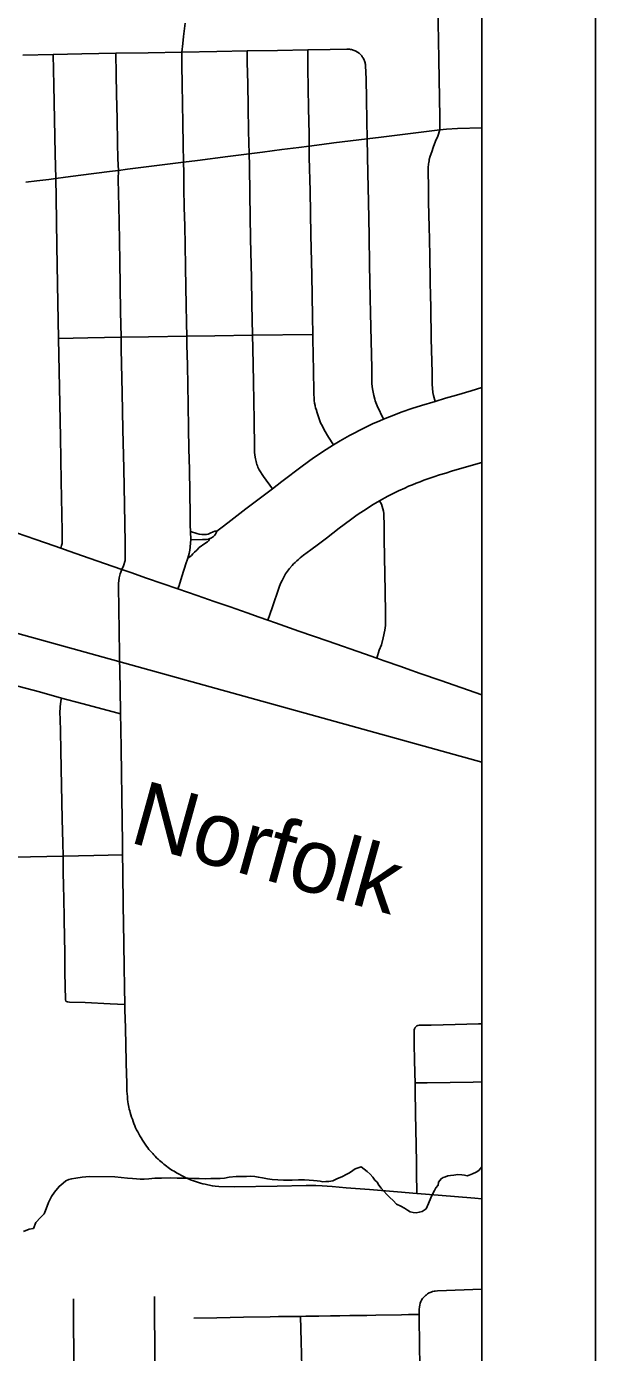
# Model space of a CAD drawing. Extents: x 0 to 34, y -1.2 to 22.
# Drawn here: x 8.499 to 9, y 18.774 to 19.941 of the extents above; entities that cross this region are included whole.
import ezdxf

# ---------------------------------------------------------------- set-up
doc = ezdxf.new("R2010")
doc.units = 0
for name, color, linetype in [('GM_X_City_Street', 7, 'Continuous'), ('GM_X_County_Road', 7, 'Continuous'), ('GM_X_Rail_Line', 7, 'Continuous'), ('GM_X_Rail_Line_Text', 7, 'Continuous'), ('GM_X_State_Route', 7, 'Continuous'), ('SH_Data', 7, 'Continuous')]:
    doc.layers.add(name, color=color, linetype=linetype)

msp = doc.modelspace()

# ---------------------------------------------------------------- linework, layer by layer
at = {"layer": 'GM_X_City_Street'}
for points in [[(8.859, 19.6109), (8.8576, 19.6159), (8.857, 19.6187), (8.8566, 19.6224), (8.8564, 19.6258), (8.8562, 19.636), (8.8555, 19.6662), (8.8554, 19.6744), (8.8551, 19.6847), (8.855, 19.6951), (8.8548, 19.7029), (8.8545, 19.7171), (8.8542, 19.7396), (8.8539, 19.7526), (8.8537, 19.7653), (8.8535, 19.774), (8.8532, 19.7877), (8.8531, 19.8001), (8.8528, 19.8127), (8.8529, 19.8176), (8.853, 19.8188), (8.8531, 19.82), (8.8533, 19.8213), (8.8536, 19.8225), (8.8538, 19.8237), (8.8547, 19.8268), (8.8559, 19.8305), (8.8573, 19.8343), (8.8593, 19.84), (8.8612, 19.8443), (8.8631, 19.85), (8.8631, 19.86), (8.8629, 19.8789), (8.8626, 19.8939), (8.8622, 19.9123), (8.862, 19.9284), (8.8614, 19.9599)], [(8.4962, 19.9157), (8.5228, 19.9163), (8.5481, 19.9167), (8.5781, 19.9173), (8.6064, 19.9178), (8.636, 19.9183), (8.6669, 19.9189), (8.6934, 19.9194), (8.7203, 19.9199), (8.7468, 19.9204), (8.7667, 19.9208), (8.7811, 19.921), (8.7836, 19.9209), (8.7845, 19.9208), (8.7853, 19.9206), (8.7861, 19.9204), (8.7869, 19.9202), (8.7877, 19.9199), (8.7885, 19.9196), (8.7892, 19.9192), (8.7907, 19.9184)], [(8.5295, 19.4815), (8.5303, 19.4841), (8.5307, 19.4858), (8.5309, 19.4876), (8.5308, 19.4966), (8.53, 19.5407), (8.5293, 19.5795), (8.5285, 19.6232), (8.5276, 19.6662), (8.527, 19.6977), (8.5262, 19.7479), (8.5255, 19.7903), (8.5252, 19.8071), (8.5247, 19.8288), (8.524, 19.8589), (8.5234, 19.8892), (8.5228, 19.9163)], [(8.5834, 19.4629), (8.5848, 19.4662), (8.5863, 19.4709), (8.5861, 19.4863), (8.5855, 19.5197), (8.5849, 19.5518), (8.5841, 19.5861), (8.5836, 19.6185), (8.5827, 19.6568), (8.5826, 19.6673), (8.5822, 19.6899), (8.5814, 19.7342), (8.5808, 19.7696), (8.5801, 19.8066), (8.5802, 19.8142), (8.5797, 19.8243), (8.5795, 19.8386), (8.5792, 19.8597), (8.5787, 19.8814), (8.5783, 19.8986), (8.5781, 19.9173)], [(8.7157, 19.534), (8.7078, 19.5447), (8.704, 19.5505), (8.7035, 19.5517), (8.703, 19.5529), (8.7025, 19.5541), (8.7021, 19.5553), (8.7017, 19.5566), (8.7014, 19.5578), (8.7011, 19.5591), (8.7008, 19.5603), (8.7005, 19.5616), (8.7003, 19.5638), (8.7001, 19.566), (8.6999, 19.5704), (8.6996, 19.594), (8.6991, 19.6281), (8.6984, 19.6576), (8.6981, 19.6691), (8.6977, 19.6964), (8.6973, 19.7197), (8.6966, 19.754), (8.6958, 19.7931), (8.6955, 19.8186), (8.6954, 19.8288), (8.6948, 19.8488), (8.6945, 19.87), (8.694, 19.8906), (8.6936, 19.9093), (8.6934, 19.9194)], [(8.7695, 19.5726), (8.7652, 19.5795), (8.7613, 19.5859), (8.7597, 19.589), (8.7589, 19.5905), (8.7582, 19.5921), (8.7569, 19.5954), (8.7563, 19.5972), (8.7551, 19.6009), (8.7542, 19.6039), (8.7538, 19.605), (8.7533, 19.6072), (8.7529, 19.6094), (8.7526, 19.6117), (8.7522, 19.6192), (8.7518, 19.638), (8.7517, 19.6515), (8.7514, 19.6662), (8.7513, 19.6697), (8.751, 19.6856), (8.7503, 19.7224), (8.7496, 19.7571), (8.7489, 19.7961), (8.7482, 19.8256), (8.7482, 19.8355), (8.7481, 19.8461), (8.7475, 19.869), (8.7468, 19.9043), (8.7468, 19.9204)], [(8.8134, 19.5951), (8.8079, 19.6069), (8.8073, 19.6084), (8.8062, 19.6114), (8.8058, 19.6129), (8.805, 19.6159), (8.8043, 19.6189), (8.804, 19.6203), (8.8038, 19.6218), (8.8032, 19.6262), (8.8032, 19.6277), (8.8031, 19.64), (8.8026, 19.6642), (8.8021, 19.6884), (8.8019, 19.7019), (8.8013, 19.7307), (8.8008, 19.7567), (8.8002, 19.7865), (8.7997, 19.8119), (8.7992, 19.842), (8.7988, 19.858), (8.7985, 19.8773), (8.7981, 19.8946), (8.7978, 19.9066), (8.7977, 19.9074), (8.7975, 19.9082), (8.7973, 19.909), (8.7971, 19.9098), (8.7968, 19.9106), (8.7965, 19.9114), (8.7961, 19.9122), (8.7957, 19.9129), (8.7953, 19.9136), (8.7948, 19.9143), (8.7943, 19.915), (8.7938, 19.9157), (8.7933, 19.9163), (8.7927, 19.9169), (8.792, 19.9174), (8.7907, 19.9184)], [(8.5276, 19.6662), (8.5533, 19.6667), (8.5826, 19.6673), (8.6066, 19.6677), (8.6404, 19.6683), (8.665, 19.6687), (8.6981, 19.6691), (8.7513, 19.6697)], [(8.6668, 19.4965), (8.6727, 19.501), (8.6792, 19.506), (8.6924, 19.5162), (8.7063, 19.5267), (8.7157, 19.534), (8.724, 19.5404), (8.7418, 19.5537), (8.752, 19.5612), (8.763, 19.5686), (8.7695, 19.5726), (8.7755, 19.5762), (8.7837, 19.5809), (8.7967, 19.5876), (8.8039, 19.591), (8.8102, 19.5938), (8.8134, 19.5951), (8.8189, 19.5974), (8.8299, 19.6016), (8.8383, 19.6045), (8.8469, 19.6073), (8.859, 19.6109), (8.8681, 19.6136), (8.8778, 19.6163), (8.8906, 19.6201), (8.9, 19.6232)], [(8.7118, 19.4183), (8.7154, 19.4291), (8.7218, 19.4474), (8.723, 19.4504), (8.7243, 19.4533), (8.7257, 19.4561), (8.7273, 19.4589), (8.729, 19.4615), (8.7308, 19.4638), (8.7331, 19.4663), (8.7344, 19.4677), (8.7358, 19.4691), (8.7373, 19.4704), (8.7387, 19.4717), (8.7402, 19.473), (8.7432, 19.4754), (8.7464, 19.4778), (8.7495, 19.4802), (8.7562, 19.4851), (8.7598, 19.4878), (8.7632, 19.4904), (8.7745, 19.4991), (8.7846, 19.5067), (8.7868, 19.5083), (8.7891, 19.51), (8.7913, 19.5115), (8.7936, 19.5131), (8.7959, 19.5146), (8.8045, 19.5202), (8.8101, 19.5234), (8.8174, 19.5274), (8.822, 19.5298), (8.8243, 19.5309), (8.8267, 19.5321), (8.8323, 19.5346), (8.8356, 19.5361), (8.839, 19.5375), (8.8423, 19.5388), (8.8457, 19.5401), (8.849, 19.5414), (8.8524, 19.5427), (8.8577, 19.5444), (8.8629, 19.5461), (8.8682, 19.5478), (8.8734, 19.5493), (8.8928, 19.555), (8.9, 19.5571)], [(8.8075, 19.3848), (8.8098, 19.3917), (8.8116, 19.3964), (8.8132, 19.4028), (8.8148, 19.4095), (8.8152, 19.4135), (8.8154, 19.4227), (8.8149, 19.4453), (8.8148, 19.4572), (8.8144, 19.4752), (8.8141, 19.4885), (8.814, 19.5008), (8.8137, 19.5121), (8.8134, 19.5142), (8.813, 19.5163), (8.8124, 19.5184), (8.8117, 19.5204), (8.8101, 19.5234)], [(8.6438, 19.4962), (8.6493, 19.4945), (8.6514, 19.494), (8.6537, 19.4936), (8.6579, 19.4938), (8.6593, 19.4941), (8.661, 19.4947), (8.6635, 19.496), (8.6651, 19.4965), (8.6668, 19.4965)], [(8.6439, 19.489), (8.6541, 19.4892), (8.6578, 19.4893), (8.6596, 19.4896), (8.6608, 19.49), (8.6617, 19.4904), (8.6635, 19.4917), (8.6648, 19.4928), (8.6658, 19.494), (8.6664, 19.4952), (8.6668, 19.4965)], [(8.6413, 19.4729), (8.643, 19.474), (8.6446, 19.4752), (8.6458, 19.4766), (8.6472, 19.4781), (8.6493, 19.48), (8.6514, 19.4821), (8.6564, 19.4858), (8.6585, 19.4873), (8.6595, 19.4882), (8.6601, 19.4889), (8.6608, 19.49)], [(8.5341, 19.0829), (8.5336, 19.0841), (8.5332, 19.1079), (8.533, 19.1249), (8.5324, 19.1543), (8.5321, 19.175), (8.5319, 19.1825), (8.5317, 19.1982), (8.5315, 19.2104), (8.5314, 19.2222), (8.5309, 19.2431), (8.5302, 19.273), (8.5299, 19.2873), (8.5295, 19.3042), (8.5292, 19.32), (8.5289, 19.3318), (8.5288, 19.3365), (8.529, 19.3419), (8.5296, 19.3469), (8.5303, 19.3497)], [(8.3359, 19.2073), (8.3493, 19.2077), (8.3639, 19.208), (8.3913, 19.2084), (8.4198, 19.2088), (8.4482, 19.2092), (8.4768, 19.2097), (8.5029, 19.21), (8.5315, 19.2104), (8.5587, 19.211), (8.5839, 19.2115)], [(8.5341, 19.0829), (8.5347, 19.0825), (8.5355, 19.0822), (8.5372, 19.082), (8.551, 19.0816), (8.5729, 19.0806), (8.5858, 19.08)], [(8.8427, 18.9135), (8.8426, 18.9319), (8.8425, 18.9404), (8.8421, 18.956), (8.8417, 18.9835), (8.8415, 19.0045), (8.8414, 19.0108), (8.8412, 19.0194), (8.8408, 19.0313), (8.8406, 19.0443), (8.8405, 19.051), (8.8406, 19.0576), (8.8408, 19.0584), (8.8411, 19.059), (8.8413, 19.0594), (8.8415, 19.0597), (8.8418, 19.0601), (8.8427, 19.061)], [(8.8427, 19.061), (8.8438, 19.0614), (8.8448, 19.0616), (8.8553, 19.0618), (8.8765, 19.0623), (8.8972, 19.0628), (8.9, 19.0629)], [(8.8414, 19.0108), (8.852, 19.011), (8.8925, 19.0116), (8.9, 19.0118)], [(8.5423, 18.5793), (8.5422, 18.5968), (8.5421, 18.6183), (8.542, 18.65), (8.5417, 18.682), (8.5415, 18.7141), (8.5413, 18.7443), (8.5411, 18.773), (8.5408, 18.7991), (8.5406, 18.8207)], [(8.6138, 18.5808), (8.6137, 18.5894), (8.6136, 18.6111), (8.6134, 18.6355), (8.6133, 18.6551), (8.613, 18.6752), (8.6129, 18.6943), (8.6127, 18.7109), (8.6125, 18.7281), (8.6124, 18.7448), (8.6124, 18.7583), (8.6123, 18.7775), (8.6122, 18.7853), (8.6121, 18.8007), (8.6119, 18.8229)], [(8.6465, 18.8038), (8.6669, 18.8041), (8.6903, 18.8047), (8.7139, 18.805), (8.7212, 18.8051), (8.7327, 18.8052), (8.7406, 18.8052), (8.7452, 18.8054), (8.7567, 18.8055), (8.7668, 18.8057), (8.7751, 18.8058), (8.7838, 18.806), (8.7915, 18.8061), (8.7989, 18.8062), (8.8068, 18.8064), (8.8293, 18.8067), (8.8356, 18.8068), (8.8448, 18.8069)], [(8.7449, 18.5826), (8.7444, 18.6057), (8.744, 18.6275), (8.7437, 18.6464), (8.7434, 18.6717), (8.7428, 18.6956), (8.7422, 18.7164), (8.7421, 18.7285), (8.7418, 18.7493), (8.7416, 18.7609), (8.7411, 18.7832), (8.7406, 18.8052)]]:
    msp.add_lwpolyline(points, dxfattribs=at)
at = {"layer": 'GM_X_County_Road'}
for p, q in [((8.586, 19.0732), (8.5858, 19.08)), ((8.8494, 18.8226), (8.8505, 18.8237))]:
    msp.add_line(p, q, dxfattribs=at)
for points in [[(8.6413, 19.4729), (8.6424, 19.477), (8.643, 19.4799), (8.6434, 19.4826), (8.6437, 19.4864), (8.6439, 19.489), (8.6438, 19.4962), (8.6435, 19.5019), (8.6433, 19.5108), (8.6427, 19.5509), (8.6422, 19.5692), (8.6419, 19.587), (8.6415, 19.6082), (8.6412, 19.6251), (8.6409, 19.6427), (8.6405, 19.6607), (8.6404, 19.6663), (8.6404, 19.6683), (8.6402, 19.6797), (8.64, 19.6962), (8.6397, 19.711), (8.6393, 19.7295), (8.6389, 19.7484), (8.6386, 19.7654), (8.6382, 19.7817), (8.6379, 19.7985), (8.6377, 19.8124), (8.6375, 19.8215), (8.6373, 19.8366), (8.6368, 19.8559), (8.6362, 19.8899), (8.6361, 19.9072), (8.636, 19.9183), (8.6368, 19.9258), (8.6375, 19.932), (8.6389, 19.9437)], [(8.4987, 19.804), (8.5085, 19.805), (8.5189, 19.8063), (8.5252, 19.8071), (8.5337, 19.8082), (8.5471, 19.81), (8.5724, 19.8132), (8.5802, 19.8142), (8.5882, 19.8152), (8.6257, 19.82), (8.6375, 19.8215), (8.6499, 19.823), (8.6765, 19.8264), (8.6954, 19.8288), (8.707, 19.8302), (8.7241, 19.8325), (8.7391, 19.8344), (8.7482, 19.8355), (8.7591, 19.8369), (8.7699, 19.8384), (8.7992, 19.842), (8.8115, 19.8435), (8.8442, 19.8477), (8.8631, 19.85), (8.8688, 19.8505), (8.8786, 19.8511), (8.9, 19.8516)], [(8.6325, 19.4458), (8.6336, 19.4489), (8.636, 19.4566), (8.64, 19.4686), (8.6407, 19.4712), (8.6413, 19.4729)], [(8.5823, 19.3229), (8.5821, 19.3359), (8.5819, 19.3583), (8.5813, 19.3861), (8.5809, 19.4112), (8.5806, 19.4259), (8.5804, 19.4506), (8.5808, 19.4554), (8.5819, 19.4589), (8.5834, 19.4629)], [(8.5834, 19.4629), (8.5911, 19.4601), (8.6049, 19.4553), (8.6325, 19.4458)], [(8.3531, 19.3974), (8.3609, 19.3952), (8.3833, 19.3892), (8.4006, 19.3846), (8.4176, 19.3802), (8.4633, 19.3676), (8.475, 19.3645), (8.4861, 19.3616), (8.5107, 19.355), (8.5303, 19.3497), (8.5481, 19.3449), (8.5755, 19.3375), (8.5821, 19.3359)], [(8.5858, 19.08), (8.5857, 19.0948), (8.5853, 19.1137), (8.5847, 19.1521), (8.5845, 19.1665), (8.5841, 19.1973), (8.5839, 19.2115), (8.5838, 19.2222), (8.5835, 19.2418), (8.5826, 19.3048), (8.5823, 19.3229)], [(8.9, 18.9088), (8.8938, 18.9093), (8.8615, 18.912), (8.8427, 18.9135), (8.8257, 18.9149), (8.8012, 18.9169), (8.7807, 18.9186), (8.7683, 18.9196), (8.7596, 18.9203), (8.7541, 18.9206), (8.7455, 18.9205), (8.72, 18.92), (8.682, 18.9193), (8.6686, 18.9196), (8.6655, 18.9199), (8.6629, 18.9202), (8.6588, 18.9211), (8.6567, 18.9216), (8.6545, 18.9221), (8.6526, 18.9226), (8.6508, 18.9231), (8.649, 18.9236), (8.6473, 18.9242), (8.6455, 18.9249), (8.6437, 18.9256), (8.642, 18.9263), (8.6403, 18.9271), (8.638, 18.9282), (8.6358, 18.9293), (8.6336, 18.9305), (8.6314, 18.9318), (8.6292, 18.933), (8.6278, 18.9338), (8.6265, 18.9346), (8.6252, 18.9355), (8.6239, 18.9364), (8.6227, 18.9374), (8.6215, 18.9384), (8.6203, 18.9394), (8.6189, 18.9404), (8.6176, 18.9415), (8.6163, 18.9426), (8.6151, 18.9438), (8.6139, 18.945), (8.6127, 18.9462), (8.6115, 18.9474), (8.6104, 18.9486), (8.6093, 18.9498), (8.6082, 18.9511), (8.6071, 18.9523), (8.6061, 18.9536), (8.6051, 18.955), (8.6038, 18.9568), (8.6026, 18.9586), (8.6014, 18.9605), (8.6002, 18.9624), (8.5991, 18.9643), (8.5981, 18.9661), (8.5972, 18.9678), (8.5963, 18.9696), (8.5954, 18.9713), (8.5946, 18.9731), (8.5938, 18.9751), (8.5931, 18.977), (8.5925, 18.9789), (8.5918, 18.9808), (8.5912, 18.9828), (8.5907, 18.9848), (8.5902, 18.9863), (8.5898, 18.9878), (8.5895, 18.9894), (8.5891, 18.9909), (8.5889, 18.9925), (8.5886, 18.9941), (8.5883, 18.9965), (8.5881, 18.9989), (8.5879, 19.0013), (8.5878, 19.0037), (8.5877, 19.007), (8.5876, 19.0104), (8.5871, 19.0283), (8.5867, 19.0454), (8.5861, 19.0693), (8.586, 19.0732)], [(8.8456, 18.7623), (8.8453, 18.7793), (8.8452, 18.7851), (8.8449, 18.7992), (8.8448, 18.8069), (8.8449, 18.8114), (8.8452, 18.8138), (8.8454, 18.8153), (8.8458, 18.8168), (8.8464, 18.8183), (8.847, 18.8197), (8.8479, 18.821), (8.8494, 18.8226)], [(8.8505, 18.8237), (8.8509, 18.8241), (8.8516, 18.8246), (8.8523, 18.8251), (8.853, 18.8256), (8.8537, 18.826), (8.8553, 18.8267), (8.8567, 18.8271), (8.8583, 18.8275), (8.859, 18.8276), (8.861, 18.8278), (8.9, 18.8292)]]:
    msp.add_lwpolyline(points, dxfattribs=at)
at = {"layer": 'GM_X_Rail_Line'}
msp.add_lwpolyline([(6.5604, 19.9276), (7.9897, 19.5428), (8.3815, 19.4371), (8.9, 19.2933)], dxfattribs=at)
at = {"layer": 'GM_X_State_Route'}
for points in [[(8.5834, 19.4629), (8.5679, 19.4681), (8.5486, 19.4748), (8.5369, 19.479), (8.5295, 19.4815), (8.5236, 19.4836), (8.5077, 19.4892), (8.4906, 19.4951)], [(8.6325, 19.4458), (8.6049, 19.4553), (8.5911, 19.4601), (8.5834, 19.4629)], [(8.8343, 19.3754), (8.8287, 19.3773), (8.814, 19.3825), (8.8075, 19.3848), (8.7969, 19.3885), (8.7649, 19.3997), (8.739, 19.4086), (8.7185, 19.4159), (8.7118, 19.4183), (8.7042, 19.4209), (8.6934, 19.4246), (8.6785, 19.4299), (8.6646, 19.4347), (8.6494, 19.44), (8.6325, 19.4458)], [(8.9, 19.3525), (8.8639, 19.3651), (8.8457, 19.3714), (8.8343, 19.3754)]]:
    msp.add_lwpolyline(points, dxfattribs=at)
at = {"layer": 'SH_Data'}
for p, q in [((9, 21), (9, 14)), ((8.9, 20.9), (8.9, 14.1))]:
    msp.add_line(p, q, dxfattribs=at)
for points in [[(8.4968, 18.88), (8.5017, 18.882), (8.5055, 18.8828), (8.5077, 18.8878), (8.5118, 18.8924), (8.5148, 18.8955), (8.5166, 18.9001), (8.5188, 18.9054), (8.5214, 18.9108), (8.524, 18.9146), (8.5281, 18.9197), (8.5315, 18.9227), (8.5341, 18.9247), (8.5367, 18.9259), (8.539, 18.9263), (8.5428, 18.9271), (8.5485, 18.9279), (8.5549, 18.9284), (8.577, 18.928), (8.5827, 18.9277), (8.5881, 18.927), (8.5926, 18.9267), (8.5961, 18.9264), (8.5995, 18.926), (8.6029, 18.9261), (8.6071, 18.9265), (8.6124, 18.927), (8.6181, 18.9271), (8.6261, 18.9272), (8.6318, 18.9269), (8.6367, 18.927), (8.6417, 18.927), (8.6463, 18.9267), (8.6512, 18.9268), (8.6565, 18.9265), (8.6615, 18.9266), (8.666, 18.9266), (8.6698, 18.9267), (8.6736, 18.9271), (8.6778, 18.9279), (8.6839, 18.9284), (8.6884, 18.9285), (8.693, 18.9285), (8.6964, 18.9286), (8.7002, 18.9283), (8.7033, 18.9279), (8.7071, 18.9272), (8.7113, 18.9265), (8.7155, 18.9258), (8.7204, 18.9255), (8.7254, 18.9252), (8.733, 18.9253), (8.7387, 18.9254), (8.744, 18.9255), (8.7482, 18.9252), (8.752, 18.9248), (8.7551, 18.9245), (8.7577, 18.9242), (8.76, 18.9238), (8.7627, 18.9239), (8.7653, 18.9239), (8.7688, 18.9247), (8.7725, 18.9263), (8.7774, 18.9283), (8.7805, 18.9302), (8.7835, 18.9318), (8.7865, 18.9337), (8.7887, 18.9353), (8.7937, 18.9369), (8.7964, 18.935), (8.799, 18.9328), (8.8017, 18.9305), (8.8041, 18.9279), (8.806, 18.9253), (8.808, 18.9234), (8.8095, 18.9207), (8.8115, 18.9181), (8.8138, 18.9155)], [(8.8138, 18.9155), (8.8165, 18.9125), (8.8192, 18.9099), (8.8219, 18.9072), (8.825, 18.9042), (8.8288, 18.9024), (8.8319, 18.9005), (8.8346, 18.8987), (8.8369, 18.8972), (8.8396, 18.8968), (8.8422, 18.8965), (8.8449, 18.8969), (8.8475, 18.8977), (8.8509, 18.9), (8.8531, 18.9046), (8.855, 18.9096), (8.8568, 18.9135), (8.8583, 18.9161), (8.8594, 18.9184), (8.8616, 18.9208), (8.862, 18.9234), (8.8642, 18.9265), (8.8661, 18.9277), (8.868, 18.9281), (8.8702, 18.9289), (8.8725, 18.9293), (8.8755, 18.9297), (8.879, 18.9301), (8.8824, 18.9298), (8.8847, 18.9295), (8.887, 18.9291), (8.8889, 18.9295), (8.8919, 18.9307), (8.8949, 18.9323), (8.8975, 18.9338), (8.9, 18.937)]]:
    msp.add_lwpolyline(points, dxfattribs=at)

# ---------------------------------------------------------------- texts
at = {"layer": 'GM_X_Rail_Line_Text'}
msp.add_text('Norfolk', height=0.05663, rotation=344.5016, dxfattribs=at).set_placement((8.5886, 19.223))

doc.saveas('drawing.dxf')
